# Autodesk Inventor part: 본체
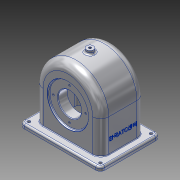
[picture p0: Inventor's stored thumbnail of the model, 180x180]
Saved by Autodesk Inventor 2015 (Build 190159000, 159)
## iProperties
Created: 2016-01
Part Number: 본체
Material: 알루미늄 6061
Document SubType Name: Modeling
Designer: 601-23
Density: 2.7 g/cm^3
Appearance: 알루미늄 - 평지
Mass: 756.185 g
Surface Area: 1009.81 cm^2
Volume: 280.069 cm^3
Author: 601-23
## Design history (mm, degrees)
sketch "스케치3"
  geometry: L1 (-57, 0)-(-57, -57); L2 (57, 0)-(57, -57); L3 (57, -57)-(-57, -57); A1 r 57 centre (0, 0) between (57, 0) and (-57, 0); 1 further point
  constraints: 6 end point, 2 point on circle, 2 tangent, 2 vertical, 1 centre point, 1 coincident, 1 perpendicular
  dimensions: "d5" = 114 diameter of A1; "d7" = 57 distance from line of L3 point (0, 0)
extrude "돌출2" new body sketch "스케치3" distance "d8" = 77; taper "d9" = 0 deg
node "작업 평면2"
sketch "스케치4"
  geometry: L1 (0, 0)-(0, 77) reference; L2 (0, 77)-(114, 77) reference; L3 (114, 77)-(114, 0) reference; L4 (114, 0)-(0, 0) reference; L5 (-13, 90.5)-(127, 90.5); L6 (127, 90.5)-(127, -13.5); L7 (127, -13.5)-(-13, -13.5); L8 (-13, -13.5)-(-13, 90.5); 5 further points
  constraints: 8 end point, 4 midpoint, 2 parallel, 1 horizontal, 1 horizontal alignment, 1 perpendicular, 1 vertical alignment
  dimensions: "d10" = 140 distance of L5.start L5.end; "d11" = 104 distance of L5.end L6.end
extrude "돌출3" join sketch "스케치4" distance "d12" = 7; taper "d13" = 0 deg
fillet "모깎기1" dims "d21" = 8
fillet "모깎기2" dims "d22" = 14
feature "쉘1" dims "d41" = 5
sketch "스케치11"
  geometry: L1 (0, 0)-(13.5, 0) reference; L2 (13.5, 0)-(13.5, -7) reference; L3 (13.5, -7)-(8.5, -7) reference; L4 (8.5, -7)-(8.5, -5) reference; L5 (8.5, -5)-(-5, -5) reference; L6 (-5, -5)-(-5, 100) reference; L7 (-14, 109)-(-63, 109) reference; L8 (-72, 100)-(-72, -5) reference; L9 (-72, -5)-(-85.5, -5) reference; L10 (-85.5, -5)-(-85.5, -7) reference; L11 (-85.5, -7)-(-90.5, -7) reference; L12 (-90.5, -7)-(-90.5, 0) reference; L13 (-90.5, 0)-(-77, 0) reference; L14 (-77, 0)-(-77, 100) reference; L15 (-63, 114)-(-14, 114) reference; L16 (0, 100)-(0, 0) reference; L17 (-77, 53)-(0, 53); L18 (-5, 57)-(-5, -5) reference; L19 (-72, -5)-(-72, 57) reference; L20 (-72, 57)-(-72, 100) reference; L21 (-72, 92.747)-(-58, 81); L22 (-58, 81)-(-58, 53); L23 (-72, 92.747)-(-72, 53); L24 (-77, 87.899)-(-74, 87.899); L25 (-74, 87.899)-(-74, 53); L26 (-74, 53)-(-77, 53); L27 (-77, 53)-(-77, 87.899); A1 r 9 centre (-14, 100) between (-5, 100) and (-14, 109) reference; A2 r 9 centre (-63, 100) between (-63, 109) and (-72, 100) reference; A3 r 14 centre (-63, 100) between (-63, 114) and (-77, 100) reference; A4 r 14 centre (-14, 100) between (0, 100) and (-14, 114) reference; 1 further point
  constraints: 16 end point, 8 point on line, 3 perpendicular, 2 parallel, 1 horizontal
  dimensions: "d42" = 60 distance between parallel lines of L3 L17; "d64" = 3 distance of L24.start L24.end; "d65" = 5 distance from line of L21 L24.end; "d66" = 50 deg angle of L22 L21; "d67" = 16 distance of L22.end L25.end; "d68" = 56 diameter of L21.end L17
  node "절단 모서리 투영7"
revolve "회전4" stored, may be unused: angle "d69" = 90 deg
sketch "스케치12"
  geometry: L1 (62, -64)-(-62, -64) reference; L2 (0, -4)-(0, 30.899) reference; L3 (0, -57)-(0, 43) reference; 3 further points
  constraints: 1 coincident, 1 vertical alignment, 2 other
extrude "돌출5" cut sketch "스케치12" distance "d71" = 3; taper "d72" = 0 deg
sketch "스케치13"
  geometry: C1 r 34.899 at (0, 0) reference; 2 further points
  constraints: 1 coincident
hole "구멍1" sketch "스케치13" at (0, 0) diameter "d73" = 40; stored, may be unused: countersink angle "d77" = 90 deg, drill point angle "d79" = 118 deg; dims "d74" = 6, "d75" = 4, "d76" = 2, "d78" = 8
sketch "스케치14"
  geometry: L1 (-43, -57)-(-43, 0) reference; L2 (-43, -57)-(43, -57) reference; L3 (43, 0)-(43, -57) reference; C1 r 20 at (0, -4) reference; C2 r 31 at (0, -4); A1 r 43 centre (0, 0) between (43, 0) and (-43, 0) reference; 1 further point
  constraints: 1 centre point, 1 coincident
  dimensions: "d80" = 62 diameter of C2
extrude "돌출6" join sketch "스케치14" distance "d81" = 10; taper "d82" = 0 deg
sketch "스케치15"
  geometry: L1 (124, 0)-(0, 0) reference; L2 (127, 91)-(127, 3) reference; L3 (0, 94)-(124, 94) reference; L4 (-3, 3)-(-3, 91) reference; L5 (105, 13.5)-(19, 13.5) reference; L6 (10, 22.5)-(10, 71.5) reference; L7 (19, 80.5)-(105, 80.5) reference; L8 (114, 22.5)-(114, 71.5) reference; A1 r 3 centre (0, 3) between (-3, 3) and (0, 0) reference; A2 r 3 centre (124, 3) between (124, 0) and (127, 3) reference; A3 r 3 centre (124, 91) between (127, 91) and (124, 94) reference; A4 r 3 centre (0, 91) between (0, 94) and (-3, 91) reference; A5 r 9 centre (19, 22.5) between (10, 22.5) and (19, 13.5) reference; A6 r 9 centre (19, 71.5) between (19, 80.5) and (10, 71.5) reference; A7 r 9 centre (105, 71.5) between (114, 71.5) and (105, 80.5) reference; A8 r 9 centre (105, 22.5) between (105, 13.5) and (114, 22.5) reference; 1 further point
extrude "돌출7" join sketch "스케치15" stored distance "d83" = 10; taper "d84" = 0 deg
fillet "모깎기3" dims "d85" = 1
fillet "모깎기4" dims "d86" = 3
sketch "스케치16"
  geometry: L1 (119, 10.5)-(-5, 10.5) reference; L2 (-10, 5.5)-(-10, -82.5) reference; L3 (-5, -87.5)-(119, -87.5) reference; L4 (124, -82.5)-(124, 5.5) reference; L5 (115, -63)-(115, -14) reference; L6 (14, 1)-(100, 1) reference; L7 (-1, -63)-(-1, -14) reference; L8 (100, -78)-(14, -78) reference; L9 (14, -72)-(100, -72) reference; L10 (109, -63)-(109, -14) reference; L11 (100, -5)-(14, -5) reference; L12 (5, -14)-(5, -63) reference; A1 r 5 centre (119, 5.5) between (124, 5.5) and (119, 10.5) reference; A2 r 5 centre (-5, 5.5) between (-5, 10.5) and (-10, 5.5) reference; A3 r 5 centre (-5, -82.5) between (-10, -82.5) and (-5, -87.5) reference; A4 r 5 centre (119, -82.5) between (119, -87.5) and (124, -82.5) reference; A5 r 15 centre (100, -63) between (100, -78) and (115, -63) reference; A6 r 15 centre (100, -14) between (115, -14) and (100, 1) reference; A7 r 15 centre (14, -14) between (14, 1) and (-1, -14) reference; A8 r 15 centre (14, -63) between (-1, -63) and (14, -78) reference; A9 r 9 centre (14, -63) between (5, -63) and (14, -72) reference; A10 r 9 centre (100, -63) between (100, -72) and (109, -63) reference; A11 r 9 centre (100, -14) between (109, -14) and (100, -5) reference; A12 r 9 centre (14, -14) between (14, -5) and (5, -14) reference; 5 further points
  constraints: 4 coincident
hole "구멍2" sketch "스케치16" at (-5, 5.5), (119, 5.5), (119, -82.5), (-5, -82.5) diameter "d87" = 5; stored, may be unused: countersink angle "d91" = 90 deg, drill point angle "d93" = 118 deg; dims "d88" = 6, "d89" = 4, "d90" = 2, "d92" = 8
fillet "모깎기5" dims "d94" = 1
chamfer "모따기1" distance "d95" = 1; stored, may be unused: second distance "d96" = 2, angle "d97" = 45 deg
fillet "모깎기6" dims "d98" = 3
sketch "스케치17" dims "d99" = 56
  geometry: L1 (-67, -53)-(-53.198, -53) reference; L2 (-51.66, -52)-(-51.66, 4) reference; L3 (51.66, 4)-(51.66, -52) reference; L4 (53.198, -53)-(67, -53) reference; L5 (70, -56)-(70, -60) reference; L6 (70, -60)-(-70, -60) reference; L7 (-70, -60)-(-70, -56) reference; C1 r 21 at (0, 0) reference; C2 r 33.899 at (0, 0) reference; A1 r 3 centre (-67, -56) between (-67, -53) and (-70, -56) reference; A2 r 51.66 centre (0, 4) between (51.66, 4) and (-51.66, 4) reference; A3 r 3 centre (67, -56) between (70, -56) and (67, -53) reference; 3 further points
  constraints: 2 vertical alignment, 1 coincident, 4 other
hole "구멍3" sketch "스케치17" at (0, 28) diameter "d100" = 3.242; stored, may be unused: countersink angle "d104" = 90 deg, drill point angle "d106" = 118 deg; dims "d101" = 7, "d102" = 4, "d103" = 2, "d105" = 9
sketch "스케치18" dims "d110" = 48
  geometry: L1 (68.614, -56)-(68.614, -60) reference; L2 (68.614, -60)-(-68.614, -60) reference; L3 (-68.614, -60)-(-68.614, -56) reference; L4 (-64.179, -53)-(64.179, -53) reference; C1 r 31 at (0, 0) reference; C2 r 21 at (0, 0) reference; 3 further points
  constraints: 2 vertical alignment, 1 coincident, 4 other
hole "구멍4" sketch "스케치18" at (0, 24) diameter "d111" = 3.242; stored, may be unused: countersink angle "d115" = 90 deg, drill point angle "d117" = 118 deg; dims "d112" = 6, "d113" = 4, "d114" = 2, "d116" = 8
node "작업 평면4"
  node "작업 평면3"
sketch "스케치19"
  geometry: L1 (57, 63)-(-57, 63) reference; L2 (57, 14)-(57, 63) reference; L3 (-57, 14)-(57, 14) reference; L4 (-57, 14)-(-57, 63) reference; C1 r 6 at (0, 38.5); 2 further points
  constraints: 1 centre point, 1 horizontal alignment, 1 midpoint, 1 vertical alignment
  dimensions: "d122" = 12 diameter of C1
extrude "돌출8" join sketch "스케치19" stored distance "d123" = 10; taper "d124" = 0 deg
hole "구멍5" diameter "d127" = 4.134; stored, may be unused: countersink angle "d131" = 90 deg, drill point angle "d133" = 118 deg; dims "d125" = 10, "d126" = 10, "d128" = 10, "d129" = 4, "d130" = 2, "d132" = 33.95
sketch "스케치20"
  geometry: L1 (76.5, -60)-(76.5, -64) reference; L2 (76.5, -64)-(-27.5, -64) reference; L3 (-27.5, -64)-(-27.5, -60) reference; L4 (-24.5, -57)-(-5.385, -57) reference; L5 (0, -56)-(49, -56) reference; L6 (54.385, -57)-(73.5, -57) reference; L7 (0, -56)-(0, 0) reference; L8 (49, 0)-(0, 0) reference; L9 (49, 0)-(49, -56) reference; L10 (68.5, -64)-(-19.5, -64) reference; A1 r 3 centre (73.5, -60) between (76.5, -60) and (73.5, -57) reference; A2 r 3 centre (-24.5, -60) between (-24.5, -57) and (-27.5, -60) reference; 3 further points
  constraints: 1 midpoint, 1 vertical alignment, 3 other
  dimensions: "d134" = 30 distance from line of L2 point (24.5, -34)
feature "엠보싱1" sketch "스케치20" dims "d135" = 0.5, "d136" = 0
fillet "모깎기7" dims "d137" = 3
chamfer "모따기2" distance "d138" = 1; stored, may be unused: second distance "d139" = 2, angle "d140" = 45 deg
chamfer "모따기3" distance "d141" = 1; stored, may be unused: second distance "d142" = 2, angle "d143" = 45 deg
node "솔리드2"
pattern_circular "원형 패턴1" dims angle "d108" = 360 deg
pattern_circular "원형 패턴2" dims angle "d119" = 360 deg
node "투영된 루프1"
node "투영된 루프2"
node "투영된 루프3"
node "투영된 루프4"
node "절단 모서리 투영2"
node "절단 모서리 투영8"
node "절단 모서리 투영9"
node "절단 모서리 투영10"
node "절단 모서리 투영11"
other parameters: "d121" = -6
